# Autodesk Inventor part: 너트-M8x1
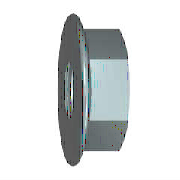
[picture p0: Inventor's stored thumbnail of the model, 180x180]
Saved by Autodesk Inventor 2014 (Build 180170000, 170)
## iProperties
Created: 2015-12
Part Number: 너트-M8x1
Material: 스테인리스강
Description: 플랜지붙이 6각 너트 - 일반 스레드
Document SubType Name: Modeling
Standard: ISO 4161
Designer: mdu
Standard Revision: 2판 1999-03-15
Standards Organization: ISO
Language: ko-KR
Size Designation: M8
Categories: <MemberInstance><Categories><Category DisplayName="조임쇠" InternalName="e4da775c-781d-43d5-af7c-5136215cf5a6" Mnemonic="FSTN"><Category DisplayName="너트" InternalN
Density: 8.08 g/cm^3
Appearance: 노란색
Author: mdu
IsCustomPart: 1
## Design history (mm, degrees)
sketch "스케치1"
  geometry: L1 (-1.844, 0)-(9.641, 0) reference; L2 (3.107, 6.5)-(2.288, 8.257); L3 (3.107, 6.5)-(8, 6.5); L4 (8, 6.5)-(8, 0); L5 (3.107, 6.5)-(3.107, 0); L6 (0, -1.835)-(0, 11.01) reference; A1 r 1.2 centre (1.2, 7.75) between (2.288, 8.257) and (0, 7.75); 1 further point
  constraints: 8 end point, 3 point on line, 2 perpendicular, 2 point on circle, 2 tangent, 1 centre point, 1 parallel
  dimensions: "d2" = 13 diameter of L3 L1 (= SW); "d4" = 17.9 dimension on A1 L1 (= LADI); "d5" = 1.2 radius of A1 (= PHH); "d15" = 8 distance between parallel lines of L4 L6 (= KOH); "d16" = 25 deg angle of L6 L2 (= KEWI)
revolve "링" sketch "스케치1" stored, may be unused: angle "d8" = 90 deg
sketch "스케치2"
  geometry: L1 (-6.5, -3.753)-(-6.5, 3.753); L2 (-6.5, 3.753)-(0, 7.506); L3 (0, 7.506)-(6.5, 3.753); L4 (6.5, 3.753)-(6.5, -3.753); L5 (6.5, -3.753)-(0, -7.506); L6 (0, -7.506)-(-6.5, -3.753); C1 r 4.9 at (0, 0); C2 r 7.75 at (0, 0) reference; 1 further point
  constraints: 12 end point, 1 centre point, 1 coincident, 1 vertical, 11 other
  dimensions: "d6" = 15.01111 distance of L5.end L2.end (= 1.1547 x SW)
extrude "본체" join sketch "스케치2" distance "d7" = 8 (= KOH); taper "d9" = 0 deg
sketch "스케치3"
  geometry: L1 (2.638, 7.506)-(8, 7.506) reference; L2 (8, 3.753)-(8, 7.506) reference; L3 (0, -7.75)-(0, 7.75) reference; L4 (-1.6, 0)-(9.6, 0) reference; L5 (7.419, 7.506)-(8, 6.5)
  constraints: 2 end point, 2 point on line
  dimensions: "d10" = 30 deg angle of L2 L5 (= ANG1); "d11" = 13 diameter of L5.end L4 (= SW0)
revolve "모따기1" sketch "스케치3" stored, may be unused: angle "d24" = 90 deg
sketch "스케치4"
  geometry: C1 r 7.75 at (0, 0) reference; 1 further point
  constraints: 1 coincident
hole "스레드" sketch "스케치4" at (0, 0) diameter "d25" = 6.647; stored, may be unused: countersink angle "d29" = 82 deg, drill point angle "d31" = 118 deg; dims "d26" = 6, "d27" = 4, "d28" = 2, "d30" = 8
workaxis "Work Axis1"
workplane "Work Plane1"
body "Solid1"
chamfer "모따기2" distance "d12" = 0.67658 (= -0.5 x GD1 + 0.5 x NND); stored, may be unused: angle "d13" = 30 deg, second distance "d46" = 0.67658 (= -0.5 x GD1 + 0.5 x NND)
chamfer "모따기3" distance "d51" = 0.67658 (= -0.5 x GD1 + 0.5 x NND); stored, may be unused: second distance "d52" = 2, angle "d53" = 45 deg
other parameters: "ANG1" = 30 deg [user parameter; used in 1 equation term], "KEWI" = 25 deg [user parameter; used in 1 equation term], "NND" = 8 [user parameter; used in 4 equation terms], "LADI" = 17.9 [user parameter; used in 2 equation terms], "SW" = 13 [user parameter; used in 3 equation terms], "PHH" = 1.2 [user parameter; used in 3 equation terms], "KOH" = 8 (= NND) [user parameter; used in 2 equation terms], "SW0" = 13 [user parameter; used in 1 equation term], "GD1" = 6.64684 (computed from THREADDIA, PTC, TOA) [user parameter; used in 3 equation terms], "d1" = 17.9 (= LADI), "d3" = 1.2 (= PHH), "d45" = 0, "d47" = 0, "d49" = 0, "d54" = 0, "GUL" = 0.67658 (= 0.541266 x PTC) [user parameter], "TPU" = 8 (computed from PTC) [user parameter], "RR" = 1.2 (= PHH) [user parameter], "THREADDIA" = 8 [user parameter; used in 1 equation term], "TOA" = 30 deg [user parameter; used in 1 equation term], "PTC" = 1.25 [user parameter; used in 4 equation terms], "GAL" = 0.67658 (= 0.541266 x PTC) [user parameter], "E0" = 15.015 (= 1.155 x SW) [user parameter]
